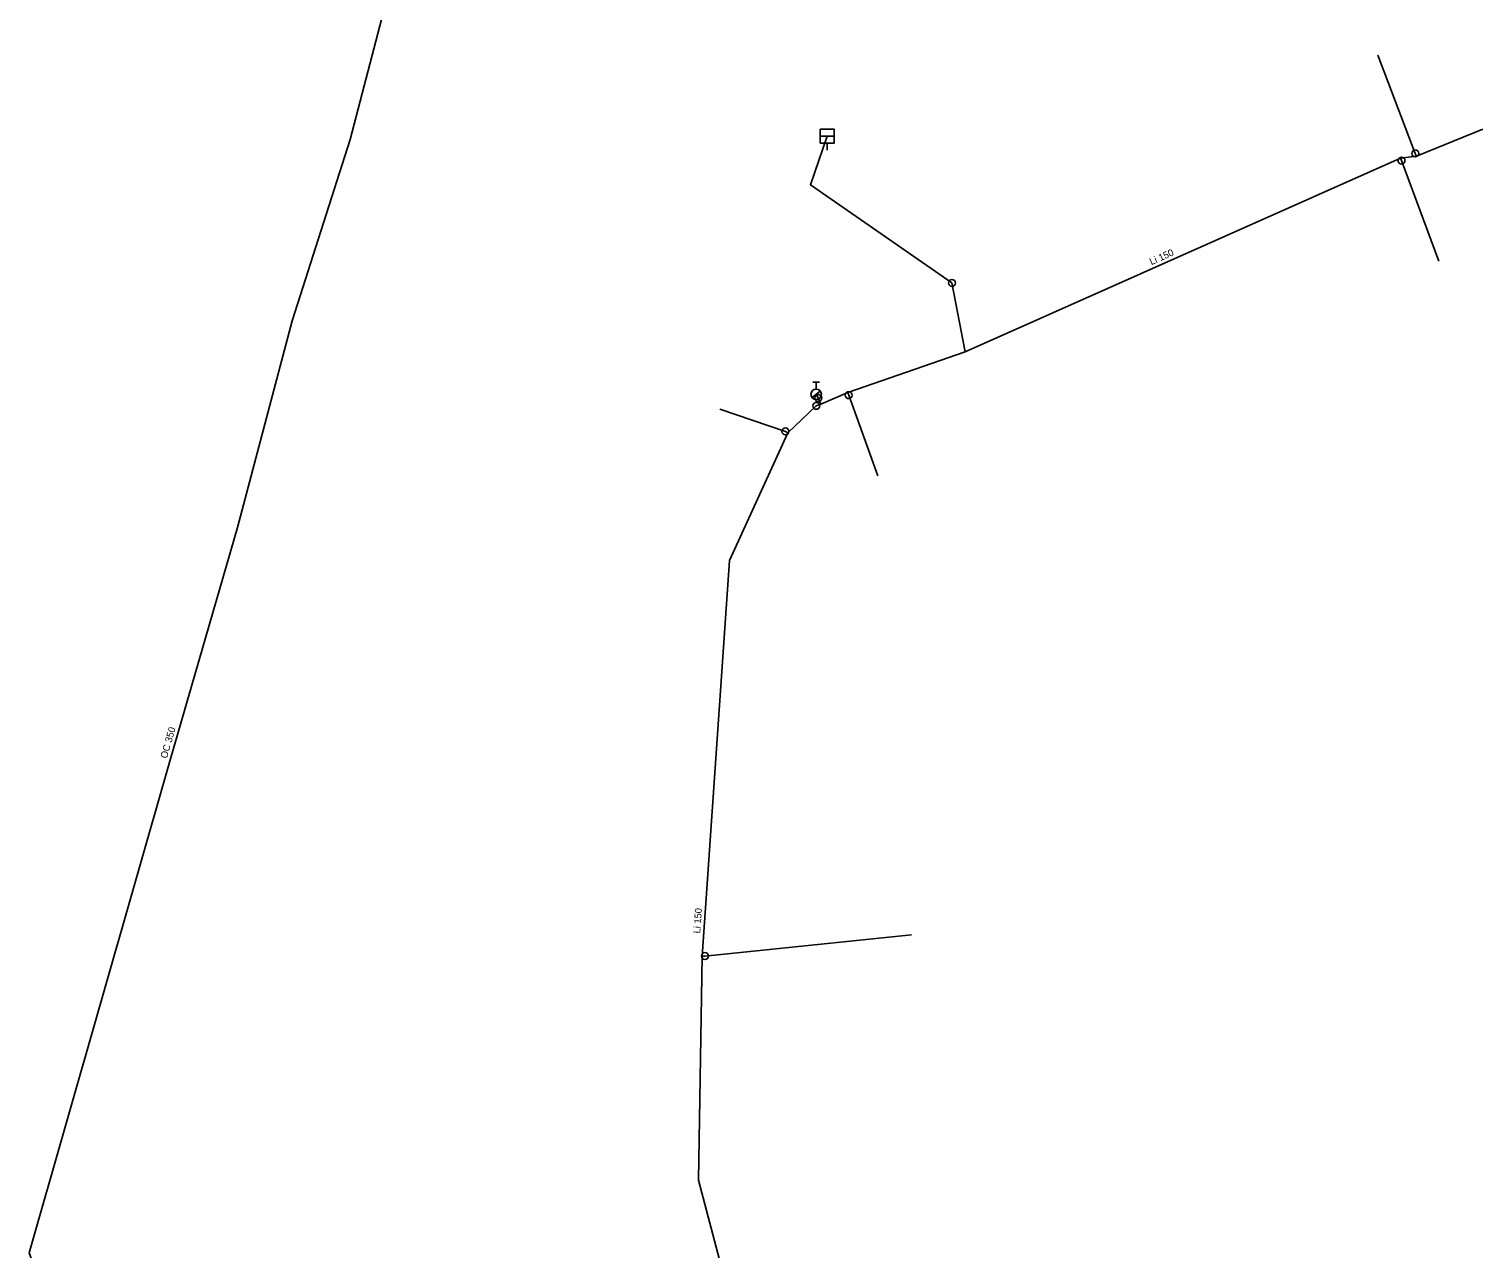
# Model space of a CAD drawing. Extents: x -770258 to -769930, y -1182247 to -1181932.
# Drawn here: x -770034.7 to -769929.9, y -1182132.7 to -1182044.8 of the extents above; entities that cross this region are included whole.
import ezdxf

# ---------------------------------------------------------------- set-up
doc = ezdxf.new("R2010")
doc.units = 0
for name, color, linetype in [('Hydranty', 7, 'Continuous'), ('Popis vodovodních řadů', 7, 'Continuous'), ('Vod přípojky-voda pitná', 7, 'Continuous'), ('Vodovodní řad', 7, 'Continuous'), ('Vodovodní šachty', 7, 'Continuous'), ('Vodovodní šoupata', 7, 'Continuous')]:
    doc.layers.add(name, color=color, linetype=linetype)

msp = doc.modelspace()

# ---------------------------------------------------------------- linework, layer by layer
at = {"layer": 'Hydranty'}
for p, q in [((-769978.2, -1182070.24), (-769977.7, -1182070.24)), ((-769977.95, -1182070.74), (-769977.95, -1182070.24)), ((-769978.24, -1182071.34), (-769977.65, -1182070.88))]:
    msp.add_line(p, q, dxfattribs=at)
msp.add_circle((-769977.95, -1182071.11), 0.375, dxfattribs=at)
at = {"layer": 'Vod přípojky-voda pitná'}
for points in [[(-769937.48, -1182046.68), (-769934.79, -1182053.75), (-769934.71, -1182053.94)], [(-769968.17, -1182063.08), (-769978.35, -1182056.02), (-769977.15, -1182052.51)], [(-769933.1, -1182061.52), (-769935.78, -1182054.27), (-769935.86, -1182054.09)], [(-769967.21, -1182068.06), (-769968.17, -1182063.08)], [(-769973.51, -1182076.97), (-769975.6, -1182071.17), (-769975.67, -1182070.98)], [(-769984.89, -1182072.17), (-769980.16, -1182073.78), (-769979.99, -1182073.88)], [(-769986.16, -1182111.58), (-769985.96, -1182111.58), (-769971.08, -1182110.06)]]:
    msp.add_lwpolyline(points, dxfattribs=at)
at = {"layer": 'Vodovodní řad'}
for points in [[(-770008.96, -1182042.91), (-770011.51, -1182052.75), (-770015.7, -1182065.81), (-770019.64, -1182080.7), (-770024.46, -1182097.37), (-770034.65, -1182132.97), (-770027.85, -1182151.54)], [(-769977.62, -1182071.81), (-769975.67, -1182070.98), (-769967.21, -1182068.06), (-769935.86, -1182054.09), (-769934.71, -1182053.94), (-769929.91, -1182052)], [(-769977.8, -1182071.37), (-769977.95, -1182071.11)], [(-769977.62, -1182071.81), (-769977.94, -1182071.94)], [(-769977.62, -1182071.81), (-769977.8, -1182071.37)], [(-769980.79, -1182149.13), (-769986.43, -1182127.72), (-769986.16, -1182111.58), (-769984.19, -1182083.09), (-769979.99, -1182073.88), (-769977.94, -1182071.94)]]:
    msp.add_lwpolyline(points, dxfattribs=at)
at = {"layer": 'Vodovodní šachty'}
msp.add_line((-769977.15, -1182053.51), (-769977.15, -1182053.01), dxfattribs=at)
msp.add_lwpolyline([(-769977.65, -1182052.51), (-769977.65, -1182052.01), (-769976.65, -1182052.01), (-769976.65, -1182052.51)], dxfattribs=at)
msp.add_lwpolyline([(-769977.65, -1182053.01), (-769976.65, -1182053.01), (-769976.65, -1182052.51), (-769977.65, -1182052.51)], close=True, dxfattribs=at)
at = {"layer": 'Vodovodní šoupata'}
for centre in [(-769935.78, -1182054.27), (-769934.79, -1182053.75), (-769968.17, -1182063.08), (-769977.94, -1182071.94), (-769977.8, -1182071.37), (-769975.6, -1182071.17), (-769980.16, -1182073.78), (-769985.96, -1182111.58)]:
    msp.add_circle(centre, 0.25, dxfattribs=at)

# ---------------------------------------------------------------- texts
at = {"layer": 'Popis vodovodních řadů'}
for s, rotation, p in [('Li 150', 24.0184, (-769953.8, -1182061.81)), ('OC 350', 74.027, (-770024.72, -1182097.38)), ('Li 150', 86.0445, (-769986.3, -1182109.96))]:
    msp.add_text(s, height=0.5, rotation=rotation, dxfattribs=at).set_placement(p)

doc.saveas('drawing.dxf')
